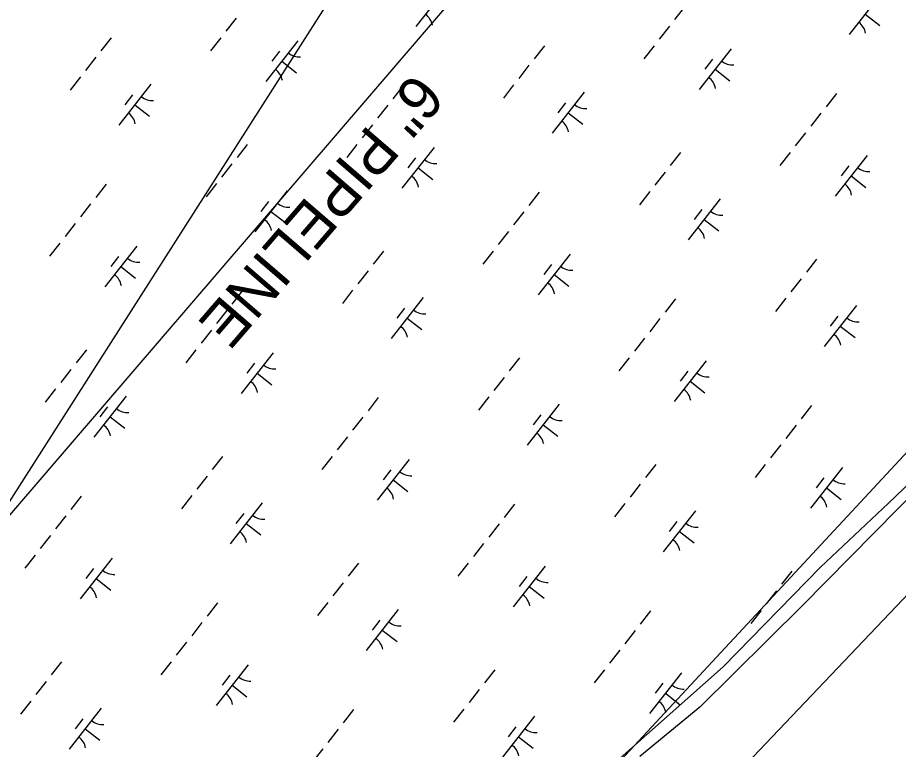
# Model space of a CAD drawing. Extents: x 3896831 to 3918110, y 171006 to 193349.
# Drawn here: x 3905103 to 3905950, y 179191 to 179895 of the extents above; entities that cross this region are included whole.
import ezdxf

# ---------------------------------------------------------------- set-up
doc = ezdxf.new("R2010")
doc.units = 0
for name, color, linetype in [('V-RIVR-EDGE', 7, 'Continuous'), ('V-RRAP-FSHR', 7, 'Continuous'), ('V-TOPO-MINR', 7, 'Continuous'), ('V-UTIL-IDEN', 7, 'Continuous'), ('V-UTIL-LINE', 7, 'Continuous'), ('V-WETL-SWMP', 7, 'Continuous')]:
    doc.layers.add(name, color=color, linetype=linetype)

msp = doc.modelspace()

# ---------------------------------------------------------------- linework, layer by layer
at = {"layer": 'V-RIVR-EDGE'}
msp.add_lwpolyline([(3905995.45, 179469.18), (3905856.99, 179328.87), (3905758.5, 179231.3), (3905700.89, 179183.91)], dxfattribs=at)
at = {"layer": 'V-RRAP-FSHR'}
msp.add_lwpolyline([(3903099.01, 175512.15), (3904431.09, 177312.94), (3905197.83, 178658.46), (3906088.44, 179617.35), (3906806.67, 180565.1), (3907065.24, 181038.97), (3907795.13, 181990.69)], dxfattribs=at)
at = {"layer": 'V-TOPO-MINR'}
msp.add_lwpolyline([(3906393.42, 179815.82), (3906366.64, 179775.28), (3906360.37, 179766.27), (3906353.82, 179757.48), (3906346.85, 179749.02), (3906339.61, 179740.78), (3906332.13, 179732.71), (3906324.63, 179724.67), (3906317.13, 179716.71), (3905327.15, 178676.1)], dxfattribs=at)
at = {"layer": 'V-UTIL-LINE'}
for points in [[(3911670.46, 187980.28), (3909726.08, 186106.61), (3909690.73, 186047.69), (3909490.4, 185423.13), (3908571.24, 184256.5), (3908123.44, 183643.73), (3907157.15, 182394.62), (3906544.37, 181593.3), (3906120.15, 181051.23), (3905460.24, 180002.44), (3904670.7, 178765.11), (3903951.87, 177622.05), (3903445.16, 176832.52), (3902962.01, 176054.77), (3902855.95, 175866.22)], [(3902278.53, 176090.12), (3904647.13, 178894.74), (3905719.49, 180143.85), (3906520.81, 181098.36), (3907322.13, 182041.09), (3907534.24, 182300.34), (3908040.96, 182924.9), (3909513.97, 184881.06), (3910138.53, 185694.16), (3909821.79, 185935.47), (3909829.34, 185945.1), (3909882.67, 185906.96)]]:
    msp.add_lwpolyline(points, dxfattribs=at)
at = {"layer": 'V-WETL-SWMP'}
for p, q in [((3905516.43, 179925.46), (3905485.58, 179886.11)), ((3905933.07, 179917.76), (3905902.23, 179878.41)), ((3905744.21, 179905.31), (3905734.34, 179892.72)), ((3905917.65, 179898.08), (3905931.82, 179886.98)), ((3905312.76, 179894.12), (3905302.89, 179881.53)), ((3905729.41, 179886.42), (3905719.54, 179873.83)), ((3905192.5, 179875.37), (3905182.63, 179862.77)), ((3905297.96, 179875.23), (3905288.09, 179862.64)), ((3905372.09, 179872.5), (3905341.25, 179833.15)), ((3905354.3, 179862.3), (3905346.9, 179852.86)), ((3905609.14, 179867.67), (3905599.27, 179855.07)), ((3905714.6, 179867.53), (3905704.73, 179854.94)), ((3905788.74, 179864.8), (3905757.89, 179825.45)), ((3905177.69, 179856.48), (3905167.82, 179843.88)), ((3905770.94, 179854.6), (3905763.54, 179845.16)), ((3905356.67, 179852.82), (3905370.84, 179841.72)), ((3905594.33, 179848.78), (3905584.46, 179836.18)), ((3905773.31, 179845.12), (3905787.48, 179834.02)), ((3905162.89, 179837.59), (3905153.02, 179824.99)), ((3905230.7, 179830.55), (3905199.86, 179791.2)), ((3905473.29, 179829.29), (3905463.42, 179816.7)), ((3905579.53, 179829.89), (3905569.66, 179817.29)), ((3905212.91, 179820.36), (3905205.51, 179810.91)), ((3905647.35, 179822.85), (3905616.5, 179783.5)), ((3905889.94, 179821.59), (3905880.07, 179809)), ((3905629.55, 179812.66), (3905622.15, 179803.21)), ((3905215.28, 179810.87), (3905229.45, 179799.77)), ((3905458.49, 179810.4), (3905448.62, 179797.81)), ((3905631.92, 179803.17), (3905646.09, 179792.07)), ((3905875.13, 179802.71), (3905865.26, 179790.11)), ((3905443.68, 179791.52), (3905433.81, 179778.92)), ((3905860.33, 179783.82), (3905850.46, 179771.22)), ((3905323.41, 179772.76), (3905313.55, 179760.16)), ((3905428.88, 179772.63), (3905419.01, 179760.03)), ((3905503.01, 179769.89), (3905472.17, 179730.54)), ((3905740.06, 179765.06), (3905730.19, 179752.46)), ((3905845.52, 179764.93), (3905835.65, 179752.33)), ((3905919.65, 179762.19), (3905888.81, 179722.84)), ((3905308.61, 179753.87), (3905298.74, 179741.27)), ((3905485.22, 179759.7), (3905477.82, 179750.25)), ((3905901.86, 179752), (3905894.46, 179742.55)), ((3905487.59, 179750.21), (3905501.76, 179739.11)), ((3905725.25, 179746.17), (3905715.38, 179733.57)), ((3905293.81, 179734.98), (3905283.94, 179722.38)), ((3905904.23, 179742.51), (3905918.4, 179731.41)), ((3905187.57, 179734.39), (3905177.7, 179721.79)), ((3905361.62, 179727.94), (3905330.78, 179688.59)), ((3905604.21, 179726.69), (3905594.34, 179714.09)), ((3905710.45, 179727.28), (3905700.58, 179714.68)), ((3905778.26, 179720.24), (3905747.42, 179680.89)), ((3905172.76, 179715.5), (3905162.89, 179702.9)), ((3905343.83, 179717.75), (3905336.43, 179708.3)), ((3905760.47, 179710.05), (3905753.07, 179700.6)), ((3905346.2, 179708.26), (3905360.37, 179697.16)), ((3905589.41, 179707.8), (3905579.54, 179695.2)), ((3905157.96, 179696.61), (3905148.09, 179684.01)), ((3905762.84, 179700.56), (3905777.01, 179689.46)), ((3905574.6, 179688.91), (3905564.73, 179676.31)), ((3905143.15, 179677.72), (3905133.28, 179665.12)), ((3905217.29, 179674.98), (3905186.44, 179635.63)), ((3905454.33, 179670.15), (3905444.46, 179657.55)), ((3905559.8, 179670.02), (3905549.93, 179657.42)), ((3905633.93, 179667.28), (3905603.09, 179627.93)), ((3905199.49, 179664.79), (3905192.09, 179655.34)), ((3905870.98, 179662.45), (3905861.11, 179649.86)), ((3905201.87, 179655.31), (3905216.03, 179644.2)), ((3905439.53, 179651.26), (3905429.66, 179638.67)), ((3905616.14, 179657.09), (3905608.73, 179647.64)), ((3905618.51, 179647.61), (3905632.68, 179636.5)), ((3905856.17, 179643.56), (3905846.3, 179630.97)), ((3905318.49, 179631.78), (3905308.62, 179619.18)), ((3905424.72, 179632.37), (3905414.85, 179619.78)), ((3905492.54, 179625.33), (3905461.7, 179585.98)), ((3905735.13, 179624.08), (3905725.26, 179611.48)), ((3905841.37, 179624.67), (3905831.5, 179612.08)), ((3905909.18, 179617.63), (3905878.34, 179578.28)), ((3905303.68, 179612.89), (3905293.81, 179600.29)), ((3905474.75, 179615.14), (3905467.34, 179605.69)), ((3905477.12, 179605.66), (3905491.29, 179594.55)), ((3905720.32, 179605.19), (3905710.45, 179592.59)), ((3905891.39, 179607.44), (3905883.99, 179597.99)), ((3905288.88, 179594), (3905279.01, 179581.41)), ((3905893.76, 179597.96), (3905907.93, 179586.85)), ((3905705.52, 179586.3), (3905695.65, 179573.71)), ((3905168.61, 179575.24), (3905158.74, 179562.65)), ((3905274.07, 179575.11), (3905264.2, 179562.52)), ((3905348.21, 179572.37), (3905317.36, 179533.02)), ((3905585.25, 179567.54), (3905575.38, 179554.95)), ((3905690.71, 179567.41), (3905680.85, 179554.82)), ((3905330.41, 179562.18), (3905323.01, 179552.73)), ((3905764.85, 179564.67), (3905734.01, 179525.32)), ((3905153.8, 179556.35), (3905143.93, 179543.76)), ((3905332.78, 179552.7), (3905346.95, 179541.59)), ((3905570.45, 179548.65), (3905560.58, 179536.06)), ((3905747.06, 179554.48), (3905739.65, 179545.03)), ((3905749.43, 179545), (3905763.59, 179533.89)), ((3905139, 179537.46), (3905129.13, 179524.87)), ((3905206.82, 179530.42), (3905175.97, 179491.07)), ((3905449.41, 179529.17), (3905439.54, 179516.58)), ((3905555.64, 179529.76), (3905545.77, 179517.17)), ((3905189.02, 179520.23), (3905181.62, 179510.78)), ((3905623.46, 179522.72), (3905592.61, 179483.37)), ((3905866.05, 179521.47), (3905856.18, 179508.88)), ((3905191.39, 179510.75), (3905205.56, 179499.64)), ((3905434.6, 179510.28), (3905424.73, 179497.69)), ((3905605.67, 179512.53), (3905598.26, 179503.08)), ((3905608.04, 179503.05), (3905622.2, 179491.94)), ((3905851.24, 179502.58), (3905841.37, 179489.99)), ((3905419.8, 179491.39), (3905409.93, 179478.8)), ((3905836.44, 179483.69), (3905826.57, 179471.1)), ((3905299.53, 179472.63), (3905289.66, 179460.04)), ((3905404.99, 179472.5), (3905395.12, 179459.91)), ((3905479.12, 179469.76), (3905448.28, 179430.41)), ((3905716.17, 179464.93), (3905706.3, 179452.34)), ((3905821.63, 179464.8), (3905811.76, 179452.21)), ((3905940.19, 179427.71), (3905979.34, 179465.22)), ((3905461.33, 179459.57), (3905453.93, 179450.13)), ((3905895.77, 179462.06), (3905864.92, 179422.71)), ((3905284.72, 179453.74), (3905274.85, 179441.15)), ((3905463.7, 179450.09), (3905477.87, 179438.98)), ((3905877.97, 179451.87), (3905870.57, 179442.43)), ((3905701.37, 179446.04), (3905691.5, 179433.45)), ((3905880.35, 179442.39), (3905894.51, 179431.28)), ((3905163.68, 179434.26), (3905153.81, 179421.67)), ((3905269.92, 179434.85), (3905260.05, 179422.26)), ((3905337.73, 179427.82), (3905306.89, 179388.46)), ((3905580.32, 179426.56), (3905570.45, 179413.97)), ((3905686.56, 179427.15), (3905676.69, 179414.56)), ((3905874.68, 179365.93), (3905940.19, 179427.71)), ((3905148.88, 179415.37), (3905139.01, 179402.78)), ((3905319.94, 179417.62), (3905312.54, 179408.18)), ((3905754.38, 179420.12), (3905723.53, 179380.76)), ((3905322.31, 179408.14), (3905336.48, 179397.04)), ((3905565.52, 179407.67), (3905555.65, 179395.08)), ((3905736.58, 179409.92), (3905729.18, 179400.48)), ((3905134.07, 179396.48), (3905124.2, 179383.89)), ((3905738.96, 179400.44), (3905753.12, 179389.34)), ((3905550.71, 179388.78), (3905540.84, 179376.19)), ((3905119.27, 179377.59), (3905109.4, 179365)), ((3905193.4, 179374.86), (3905162.56, 179335.5)), ((3905175.61, 179364.66), (3905168.2, 179355.22)), ((3905430.45, 179370.02), (3905420.58, 179357.43)), ((3905535.91, 179369.89), (3905526.04, 179357.3)), ((3905610.04, 179367.16), (3905579.2, 179327.8)), ((3905781.18, 179270.34), (3905874.68, 179365.93)), ((3905847.09, 179362.32), (3905837.22, 179349.73)), ((3905177.98, 179355.18), (3905192.15, 179344.08)), ((3905592.25, 179356.96), (3905584.85, 179347.52)), ((3905415.64, 179351.13), (3905405.77, 179338.54)), ((3905594.62, 179347.48), (3905608.79, 179336.38)), ((3905832.28, 179343.43), (3905822.41, 179330.84)), ((3905294.6, 179331.65), (3905284.73, 179319.06)), ((3905400.84, 179332.24), (3905390.97, 179319.65)), ((3905468.65, 179325.21), (3905437.81, 179285.85)), ((3905711.24, 179323.95), (3905701.37, 179311.36)), ((3905817.48, 179324.54), (3905807.61, 179311.95)), ((3905279.79, 179312.76), (3905269.92, 179300.17)), ((3905450.86, 179315.01), (3905443.46, 179305.57)), ((3905453.23, 179305.53), (3905467.4, 179294.43)), ((3905696.44, 179305.06), (3905686.57, 179292.47)), ((3905264.99, 179293.87), (3905255.12, 179281.28)), ((3905681.63, 179286.17), (3905671.76, 179273.58)), ((3905144.72, 179275.11), (3905134.85, 179262.52)), ((3905250.18, 179274.98), (3905240.31, 179262.39)), ((3905324.32, 179272.25), (3905293.47, 179232.89)), ((3905676.11, 179177.23), (3905781.18, 179270.34)), ((3905306.53, 179262.05), (3905299.12, 179252.61)), ((3905561.36, 179267.41), (3905551.49, 179254.82)), ((3905666.83, 179267.28), (3905656.96, 179254.69)), ((3905740.96, 179264.55), (3905710.12, 179225.19)), ((3905129.92, 179256.22), (3905120.05, 179243.63)), ((3905308.9, 179252.57), (3905323.06, 179241.47)), ((3905723.17, 179254.35), (3905715.77, 179244.91)), ((3905546.56, 179248.52), (3905536.69, 179235.93)), ((3905725.54, 179244.87), (3905739.71, 179233.77)), ((3905115.11, 179237.33), (3905105.24, 179224.74)), ((3905182.93, 179230.3), (3905152.08, 179190.95)), ((3905425.52, 179229.04), (3905415.65, 179216.45)), ((3905531.75, 179229.63), (3905521.88, 179217.04)), ((3905165.13, 179220.1), (3905157.73, 179210.66)), ((3905599.57, 179222.6), (3905568.73, 179183.25)), ((3905167.51, 179210.62), (3905181.67, 179199.52)), ((3905410.71, 179210.15), (3905400.84, 179197.56)), ((3905581.78, 179212.4), (3905574.38, 179202.96)), ((3905584.15, 179202.92), (3905598.32, 179191.82)), ((3905395.91, 179191.26), (3905386.04, 179178.67))]:
    msp.add_line(p, q, dxfattribs=at)
for centre, start, end in [((3905484.15, 179883.9), 11.14028, 52.68394), ((3905900.8, 179876.2), 11.14028, 52.68394), ((3905373.9, 179874.42), 231.14028, 272.68394), ((3905790.54, 179866.72), 231.14028, 272.68394), ((3905339.82, 179830.94), 11.14028, 52.68394), ((3905756.46, 179823.24), 11.14028, 52.68394), ((3905232.51, 179832.47), 231.14028, 272.68394), ((3905198.43, 179788.99), 11.14028, 52.68394), ((3905649.15, 179824.77), 231.14028, 272.68394), ((3905615.07, 179781.29), 11.14028, 52.68394), ((3905504.82, 179771.81), 231.14028, 272.68394), ((3905921.46, 179764.11), 231.14028, 272.68394), ((3905470.74, 179728.33), 11.14028, 52.68394), ((3905887.38, 179720.63), 11.14028, 52.68394), ((3905363.43, 179729.86), 231.14028, 272.68394), ((3905780.07, 179722.16), 231.14028, 272.68394), ((3905329.35, 179686.38), 11.14028, 52.68394), ((3905745.99, 179678.68), 11.14028, 52.68394), ((3905219.09, 179676.9), 231.14028, 272.68394), ((3905635.73, 179669.2), 231.14028, 272.68394), ((3905185.01, 179633.42), 11.14028, 52.68394), ((3905601.66, 179625.72), 11.14028, 52.68394), ((3905494.34, 179627.25), 231.14028, 272.68394), ((3905910.99, 179619.55), 231.14028, 272.68394), ((3905460.27, 179583.77), 11.14028, 52.68394), ((3905876.91, 179576.07), 11.14028, 52.68394), ((3905350.01, 179574.29), 231.14028, 272.68394), ((3905766.65, 179566.59), 231.14028, 272.68394), ((3905315.93, 179530.81), 11.14028, 52.68394), ((3905732.58, 179523.11), 11.14028, 52.68394), ((3905208.62, 179532.34), 231.14028, 272.68394), ((3905625.26, 179524.64), 231.14028, 272.68394), ((3905174.54, 179488.86), 11.14028, 52.68394), ((3905591.18, 179481.16), 11.14028, 52.68394), ((3905480.93, 179471.68), 231.14028, 272.68394), ((3905897.57, 179463.98), 231.14028, 272.68394), ((3905446.85, 179428.2), 11.14028, 52.68394), ((3905863.49, 179420.5), 11.14028, 52.68394), ((3905339.54, 179429.73), 231.14028, 272.68394), ((3905756.18, 179422.03), 231.14028, 272.68394), ((3905305.46, 179386.25), 11.14028, 52.68394), ((3905722.1, 179378.55), 11.14028, 52.68394), ((3905195.2, 179376.77), 231.14028, 272.68394), ((3905611.85, 179369.07), 231.14028, 272.68394), ((3905161.13, 179333.29), 11.14028, 52.68394), ((3905577.77, 179325.59), 11.14028, 52.68394), ((3905470.46, 179327.12), 231.14028, 272.68394), ((3905436.38, 179283.64), 11.14028, 52.68394), ((3905326.12, 179274.16), 231.14028, 272.68394), ((3905742.77, 179266.46), 231.14028, 272.68394), ((3905292.04, 179230.68), 11.14028, 52.68394), ((3905708.69, 179222.98), 11.14028, 52.68394), ((3905184.73, 179232.22), 231.14028, 272.68394), ((3905601.37, 179224.52), 231.14028, 272.68394), ((3905150.65, 179188.74), 11.14028, 52.68394), ((3905567.3, 179181.04), 11.14028, 52.68394)]:
    msp.add_arc(centre, 17.62, start, end, dxfattribs=at)

# ---------------------------------------------------------------- texts
at = {"layer": 'V-UTIL-IDEN'}
msp.add_text('6" PIPELINE', height=41.9999, rotation=229.21919, dxfattribs=at).set_placement((3905483.73, 179843.32))

doc.saveas('drawing.dxf')
